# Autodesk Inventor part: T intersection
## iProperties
Created: 2010-02
Part Number: T intersection
Document SubType Name: Modeling
Designer: jgehrig
Density: 1 g/cm^3
Author: jgehrig
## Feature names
1. Extrusion1
2. Extrusion2
3. Extrusion3
